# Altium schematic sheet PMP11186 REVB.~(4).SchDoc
size 431 x 279 mm; Date: Not shown in title block; ApprovedBy: Not shown in title block; CheckedBy: Not shown in title block; Author: Not shown in title block; CompanyName: Not shown in title block; Engineer: Not shown in title block; Organization: Not shown in title block; Address1: Not shown in title block; Address2: Not shown in title block; Address3: Not shown in title block; Address4: Not shown in title block; DocumentNumber: 1; Revision: Use project parameter SCH_Rev; SheetNumber: 1; SheetTotal: 1; PageSetup: Record=PageOptions¦CenterHorizontal=True¦CenterVertical=True¦PrintScale=1.00¦XCorrection=1.00¦YCorrection=1.00¦PrintKind=0¦BorderSize=5000000¦LeftOffset=0¦BottomOffset=0¦Orientation=2¦PaperLength=1000¦PaperWidth=1000¦Scale=100¦PaperSource=15¦PrintQuality=600¦MediaType=1¦DitherType=10¦PaperKind=Letter¦PrintScaleMode=1
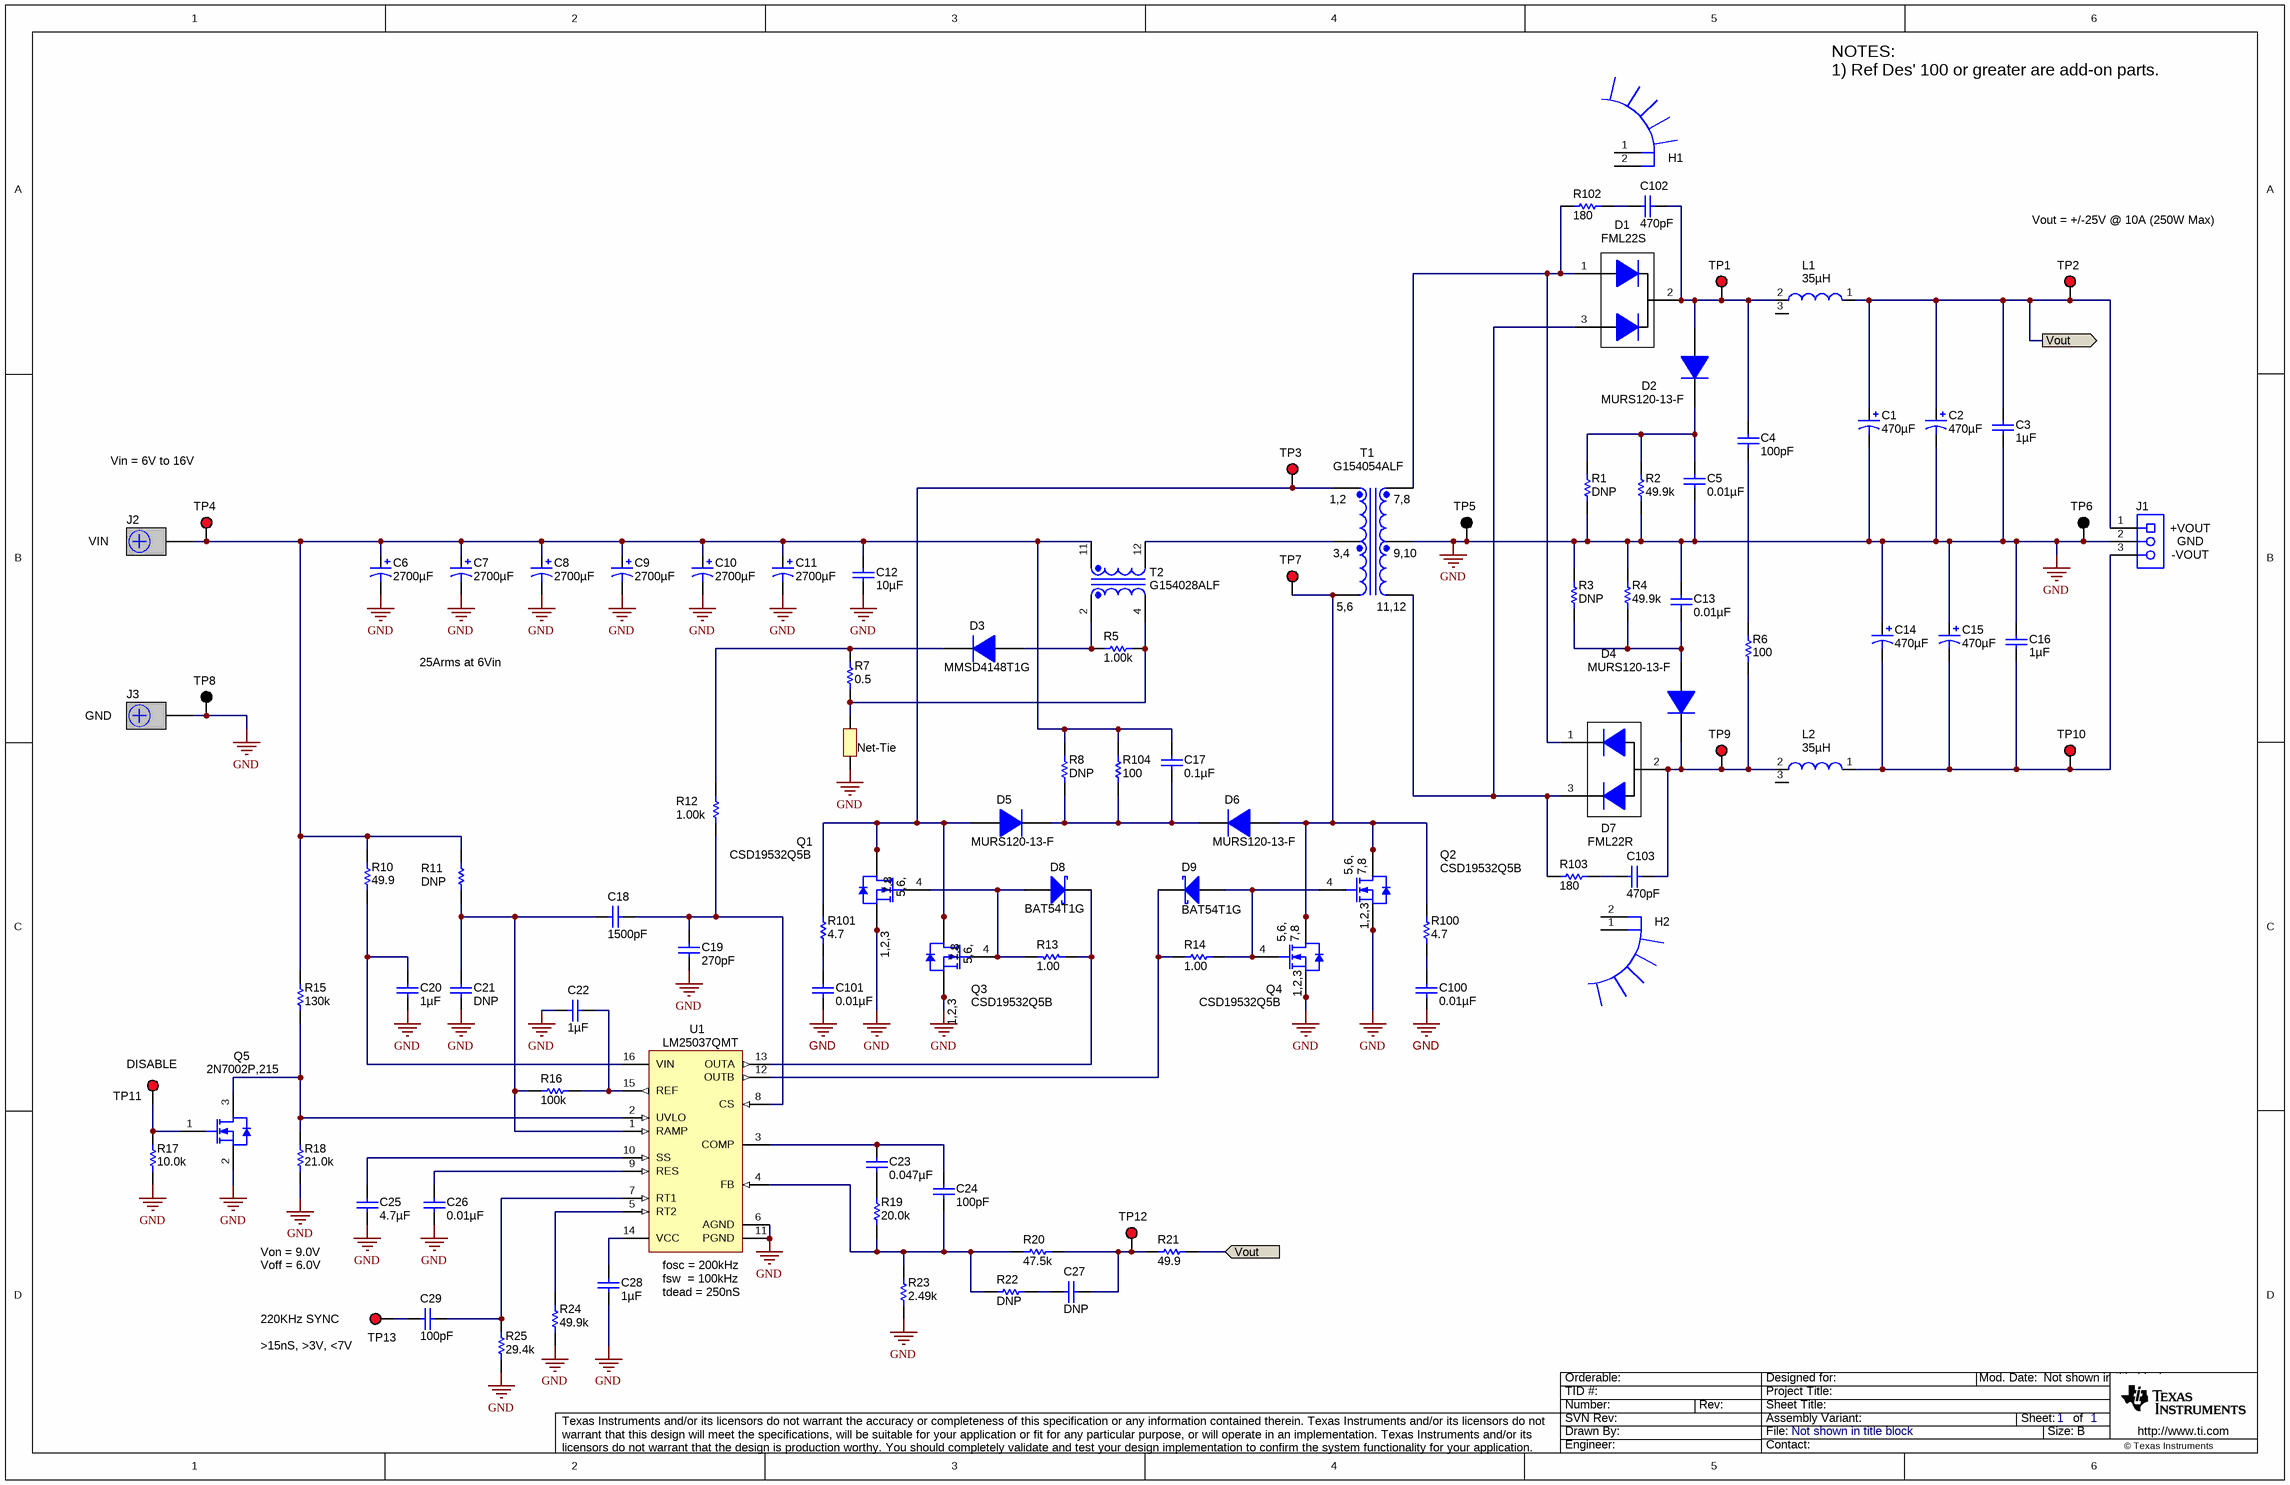
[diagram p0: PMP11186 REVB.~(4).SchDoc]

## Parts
C1  ValueDisplayed: 470µF  [CAPPR5-10X20]  (hidden comment: 35ZL470MEFC10X20)
C2  ValueDisplayed: 470µF  [CAPPR5-10X20]  (hidden comment: 35ZL470MEFC10X20)
C3  ValueDisplayed: 1µF  [0805_HV]  (hidden comment: GRM21BR71H105KA12L)
C4  ValueDisplayed: 100pF  [0805_HV]  (hidden comment: GRM21A5C2E101JW01D)
C5  ValueDisplayed: 0.01µF  [0805_HV]  (hidden comment: C2012X7R2A103M)
C6  ValueDisplayed: 2700µF  [ZLH_1250x2500]  (hidden comment: 25ZLH2700M12.5X35)
C7  ValueDisplayed: 2700µF  [ZLH_1250x2500]  (hidden comment: 25ZLH2700M12.5X35)
C8  ValueDisplayed: 2700µF  [ZLH_1250x2500]  (hidden comment: 25ZLH2700M12.5X35)
C9  ValueDisplayed: 2700µF  [ZLH_1250x2500]  (hidden comment: 25ZLH2700M12.5X35)
C10  ValueDisplayed: 2700µF  [ZLH_1250x2500]  (hidden comment: 25ZLH2700M12.5X35)
C11  ValueDisplayed: 2700µF  [ZLH_1250x2500]  (hidden comment: 25ZLH2700M12.5X35)
C12  ValueDisplayed: 10µF  [1210]  (hidden comment: C3225X7R1E106M)
C13  ValueDisplayed: 0.01µF  [0805_HV]  (hidden comment: C2012X7R2A103M)
C14  ValueDisplayed: 470µF  [CAPPR5-10X20]  (hidden comment: 35ZL470MEFC10X20)
C15  ValueDisplayed: 470µF  [CAPPR5-10X20]  (hidden comment: 35ZL470MEFC10X20)
C16  ValueDisplayed: 1µF  [0805_HV]  (hidden comment: GRM21BR71H105KA12L)
C17  ValueDisplayed: 0.1µF  [0805_145]  (hidden comment: C2012X7T2E104K125AA)
C18  ValueDisplayed: 1500pF  [0603]  (hidden comment: C1608C0G1H152J)
C19  ValueDisplayed: 270pF  [0603]  (hidden comment: C1608C0G1H271J)
C20  ValueDisplayed: 1µF  [0805_HV]  (hidden comment: C2012X7R1E105K)
C21  ValueDisplayed: DNP  [0603]
C22  ValueDisplayed: 1µF  [0603]  (hidden comment: C1608X7R1C105K)
C23  ValueDisplayed: 0.047µF  [0603]  (hidden comment: C1608X7R1H473K)
C24  ValueDisplayed: 100pF  [0603]  (hidden comment: C1608C0G1H101J)
C25  ValueDisplayed: 4.7µF  [0805_HV]  (hidden comment: C2012X7R1A475M)
C26  ValueDisplayed: 0.01µF  [0603]  (hidden comment: C1608X7R1H103K)
C27  ValueDisplayed: DNP  [0603]
C28  ValueDisplayed: 1µF  [0603]  (hidden comment: C1608X7R1C105K)
C29  ValueDisplayed: 100pF  [0603]  (hidden comment: C1608C0G1H101J)
C100  ValueDisplayed: 0.01µF  [0805_HV]  (hidden comment: C2012X7R2A103K)
C101  ValueDisplayed: 0.01µF  [0805_HV]  (hidden comment: C2012X7R2A103K)
C102  ValueDisplayed: 470pF  [0603]  (hidden comment: C1608C0G2E471J)
C103  ValueDisplayed: 470pF  [0603]  (hidden comment: C1608C0G2E471J)
D1  FML22S  [ITO-220AB]
D2  MURS120-13-F  [SMB]
D3  MMSD4148T1G  [SOD-123]
D4  MURS120-13-F  [SMB]
D5  MURS120-13-F  [SMB]
D6  MURS120-13-F  [SMB]
D7  FML22R  [ITO-220AB]
D8  BAT54T1G  [SOD-123]
D9  BAT54T1G  [SOD-123]
H1  513201B02500G  [HSINK_513201B02500]  (value not drawn)
H2  513201B02500G  [HSINK_513201B02500]  (value not drawn)
J1  OSTTA034163  [On-Shore_OSTTA034163]  (value not drawn)
J2  CB35-36-CY  [CB35-36-CY]  (value not drawn)
J3  CB35-36-CY  [CB35-36-CY]  (value not drawn)
L1  ValueDisplayed: 35µH  [B82559_1420]  (hidden comment: B82559A0353A020)
L2  ValueDisplayed: 35µH  [B82559_1420]  (hidden comment: B82559A0353A020)
NT1  Net-Tie  [Net-Tie_10mil]  (net tie, no BOM)
Q1  CSD19532Q5B  [TRANS_NexFET_Q5B]
Q2  CSD19532Q5B  [TRANS_NexFET_Q5B]
Q3  CSD19532Q5B  [TRANS_NexFET_Q5B]
Q4  CSD19532Q5B  [TRANS_NexFET_Q5B]
Q5  2N7002P,215  [SOT-23]
R1  ValueDisplayed: DNP  [1206]
R2  ValueDisplayed: 49.9k  [1206]  (hidden comment: CRCW120649K9FKEA)
R3  ValueDisplayed: DNP  [1206]
R4  ValueDisplayed: 49.9k  [1206]  (hidden comment: CRCW120649K9FKEA)
R5  ValueDisplayed: 1.00k  [0805_HV]  (hidden comment: CRCW08051K00FKEA)
R6  value 100  [1206]  (hidden comment: CRCW1206100RFKEA)
R7  ValueDisplayed: 0.5  [1206]  (hidden comment: CSR1206FKR500)
R8  ValueDisplayed: DNP  [2512]
R10  ValueDisplayed: 49.9  [0805_HV]  (hidden comment: CRCW080549R9FKEA)
R11  ValueDisplayed: DNP  [0603]
R12  ValueDisplayed: 1.00k  [0603]  (hidden comment: CRCW06031K00FKEA)
R13  value 1.00  [0603]  (hidden comment: CRCW06031R00FKEA)
R14  value 1.00  [0603]  (hidden comment: CRCW06031R00FKEA)
R15  ValueDisplayed: 130k  [0603]  (hidden comment: CRCW0603130KFKEA)
R16  ValueDisplayed: 100k  [0603]  (hidden comment: CRCW0603100KFKEA)
R17  value 10.0k  [0603]  (hidden comment: CRCW060310K0FKEA)
R18  ValueDisplayed: 21.0k  [0603]  (hidden comment: CRCW060321K0FKEA)
R19  ValueDisplayed: 20.0k  [0603]  (hidden comment: CRCW060320K0FKEA)
R20  ValueDisplayed: 47.5k  [0603]  (hidden comment: CRCW060347K5FKEA)
R21  ValueDisplayed: 49.9  [0603]  (hidden comment: CRCW060349R9FKEA)
R22  ValueDisplayed: DNP  [0603]
R23  value 2.49k  [0603]  (hidden comment: CRCW06032K49FKEA)
R24  ValueDisplayed: 49.9k  [0603]  (hidden comment: CRCW060349K9FKEA)
R25  ValueDisplayed: 29.4k  [0603]  (hidden comment: CRCW060329K4FKEA)
R100  ValueDisplayed: 4.7  [2512]  (hidden comment: CRCW25124R70JNEG)
R101  ValueDisplayed: 4.7  [2512]  (hidden comment: CRCW25124R70JNEG)
R102  ValueDisplayed: 180  [2512]  (hidden comment: CRCW2512180RFKEG)
R103  ValueDisplayed: 180  [2512]  (hidden comment: CRCW2512180RFKEG)
R104  ValueDisplayed: 100  [RESAR6600W80L4800T950H900]  (hidden comment: TMC010100R0FE02NI)
T1  G154054ALF  [GCI_G154027ALF]
T2  G154028ALF  [GCI_G154028ALF]
TP1  5000  [Keystone5000]  (value not drawn)
TP2  5000  [Keystone5000]  (value not drawn)
TP3  5000  [Keystone5000]  (value not drawn)
TP4  5000  [Keystone5000]  (value not drawn)
TP5  5001  [Keystone5001]  (value not drawn)
TP6  5001  [Keystone5001]  (value not drawn)
TP7  5000  [Keystone5000]  (value not drawn)
TP8  5001  [Keystone5001]  (value not drawn)
TP9  5000  [Keystone5000]  (value not drawn)
TP10  5000  [Keystone5000]  (value not drawn)
TP11  5000  [Keystone5000]  (value not drawn)
TP12  5000  [Keystone5000]  (value not drawn)
TP13  5000  [Keystone5000]  (value not drawn)
U1  LM25037QMT  [MTC16_N]

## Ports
Vout

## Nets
GND: C1.2(-) C2.2(-) C3.2 C5.2 C6.2(-) C7.2(-) C8.2(-) C9.2(-) C10.2(-) C11.2(-) C12.2 C13.1 C14.1(+) C15.1(+) C16.1 C19.1 C20.2 C21.1 C22.1 C25.2 C26.2 C28.2 C100.2 C101.2 J1.2 J3.1 NT1.2 Q1.1(S) Q1.2(S) Q1.3(S) Q2.1(S) Q2.2(S) Q2.3(S) Q3.1(S) Q3.2(S) Q3.3(S) Q4.1(S) Q4.2(S) Q4.3(S) Q5.2(S) R1.1 R2.1 R3.2 R4.2 R17.1 R18.1 R23.1 R24.1 R25.1 T1.2 TP5.1 TP6.1 TP8.1 U1.6(AGND) U1.11(PGND)
Vout: C1.1(+) C2.1(+) C3.1 J1.1 L1.1 R21.1 TP2.1 ; port Vout
NetC4_1: C4.1 C102.2 D1.2(K) D2.2(A) L1.2 TP1.1
NetC4_2: C4.2 R6.2
NetC5_1: C5.1 D2.1(K) R1.2 R2.2
NetC6_1: C6.1(+) C7.1(+) C8.1(+) C9.1(+) C10.1(+) C11.1(+) C12.1 C17.1 J2.1 R8.2 R10.2 R11.1 R15.2 R104.2 T2.11 TP4.1
NetC13_2: C13.2 D4.2(A) R3.1 R4.1
NetC14_2: C14.2(-) C15.2(-) C16.2 J1.3 L2.1 TP10.1
NetC17_2: C17.2 D5.1(K) D6.1(K) R8.1 R104.1
NetC18_1: C18.1 C21.2 R11.2 R16.2 U1.1(RAMP)
NetC18_2: C18.2 C19.2 R12.1 U1.8(CS)
NetC20_1: C20.1 R10.1 U1.16(VIN)
NetC22_2: C22.2 R16.1 U1.15(REF)
NetC23_1: C23.1 R19.2
NetC23_2: C23.2 C24.1 U1.3(COMP)
NetC24_2: C24.2 R19.1 R20.1 R22.1 R23.2 U1.4(FB)
NetC25_1: C25.1 U1.10(SS)
NetC26_1: C26.1 U1.9(RES)
NetC27_1: C27.1 R22.2
NetC27_2: C27.2 R20.2 R21.2 TP12.1
NetC28_1: C28.1 U1.14(VCC)
NetC29_1: C29.1 TP13.1
NetC29_2: C29.2 R25.2 U1.7(RT1)
NetC100_1: C100.1 R100.1
NetC101_1: C101.1 R101.1
NetC102_1: C102.1 R102.2
NetC103_1: C103.1 R103.2
NetC103_2: C103.2 D4.1(K) D7.2(A) L2.2 R6.1 TP9.1
NetD1_1: D1.1(A) D7.1(K) R102.1 T1.4
NetD1_3: D1.3(A) D7.3(K) R103.1 T1.6
NetD3_1: D3.1(K) R7.2 R12.2
NetD3_2: D3.2(A) R5.1 T2.2
NetD5_2: D5.2(A) Q1.5(D) Q1.6(D) Q1.7(D) Q1.8(D) Q3.5(D) Q3.6(D) Q3.7(D) Q3.8(D) R101.2 T1.1 TP3.1
NetD6_2: D6.2(A) Q2.5(D) Q2.6(D) Q2.7(D) Q2.8(D) Q4.5(D) Q4.6(D) Q4.7(D) Q4.8(D) R100.2 T1.3 TP7.1
NetD8_1: D8.1(K) R13.1 U1.13(OUTA)
NetD8_2: D8.2(A) Q1.4(G) Q3.4(G) R13.2
NetD9_1: D9.1(K) R14.1 U1.12(OUTB)
NetD9_2: D9.2(A) Q2.4(G) Q4.4(G) R14.2
NetNT1_1: NT1.1 R5.2 R7.1 T2.4
NetQ5_1: Q5.1(G) R17.2 TP11.1
NetQ5_3: Q5.3(D) R15.1 R18.2 U1.2(UVLO)
NetR24_2: R24.2 U1.5(RT2)
NetT1_5: T1.5 T2.12

Not connected (* = marked no-connect by the designer): H1 1 2; H2 1 2; L1 3; L2 3

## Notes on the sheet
- NOTES:
  1) Ref Des' 100 or greater are add-on parts.
- Vout = +/-25V @ 10A (250W Max)
- Vin = 6V to 16V
- VIN
- (near T1) 1,2
- (near T1) 3,4
- (near T1) 7,8
- (near T1) 9,10
- (near J1) +VOUT
- (near J1) -VOUT
- (near J1) GND
- (near T1) 5,6
- (near T1) 11,12
- 25Arms at 6Vin
- GND
- (near TP11) DISABLE
- Von = 9.0V
- Voff = 6.0V
- fsw  = 100kHz
- tdead = 250nS
- (near U1) fosc = 200kHz
- 220KHz SYNC
- (near TP13) >15nS, >3V, <7V

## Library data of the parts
C1 C2 C14 C15 = 35ZL470MEFC10X20: CAP, AL, 470 µF, 35 V, 0.023 Ohms, 1.82A, TH; Manufacturer: Rubycon; Polarized: Y; CompType: Capacitor; Value: 470uF; U/M: EA; Cap_F: 0.00047; Tolerance_%: 20; Value1: Unknown; VDC_V: 35; Value2: 35V; TaMin_C: -40; TaMax_C: 105; Cap_Case: 10x20
C3 C16 = GRM21BR71H105KA12L: CAP, CERM, 1uF, 50V, +/-10%, X7R, 0805; Manufacturer: MuRata; Polarized: N; CompType: Capacitor; U/M: EA; Cap_F: 0.000001; Tolerance_%: 10; VDC_V: 50; TaMin_C: -55; TaMax_C: 125; Cap_Case: 0805
C4 = GRM21A5C2E101JW01D: CAP, CERM, 100 pF, 250 V, +/- 5%, C0G/NP0, 0805; Manufacturer: MuRata; Polarized: N; CompType: Capacitor; Value: 100pF; U/M: EA; Cap_F: 0.0000000001; Tolerance_%: 5; Value1: Unknown; VDC_V: 250; Value2: 250V; TaMin_C: -55; TaMax_C: 125; Cap_Case: 0805
C5 C13 = C2012X7R2A103M: CAP, CERM, 0.01 µF, 100 V, +/- 20%, X7R, 0805; Manufacturer: TDK; Polarized: N; CompType: Capacitor; Value: 0.01uF; U/M: EA; Cap_F: 0.00000001; Tolerance_%: 20; ESR_ohm: 0.0571; Value1: 0.0571 ohm; VDC_V: 100; Value2: 100V; TaMin_C: -55; TaMax_C: 125; Cap_Case: 0805
C6-C11 = 63ZLH470M12.5X25: CAP, AL, 2700 µF, 25 V, 0.016 ohm, 4.12A, TH; Manufacturer: Rubycon; Polarized: Y; CompType: Capacitor; Value: 2700uF; U/M: EA; Cap_F: 0.00047; Tolerance_%: 20; Value2: 25V; ESR_ohm: 0.043; IRMS_A: 1.99; TaMin_C: -40; TaMax_C: 105
C12 = C3225X7R1E106M: CAP, CERM, 10 µF, 25 V, +/- 20%, X7R, 1210; Manufacturer: TDK; Polarized: N; CompType: Capacitor; Value: 10uF; U/M: EA; Cap_F: 0.00001; Tolerance_%: 20; ESR_ohm: 0.0027; Value1: 0.0027 ohm; VDC_V: 25; Value2: 25V; IRMS_A: 3; TaMin_C: -55; TaMax_C: 125
C17 = C2012X7T2E104K125AA: CAP, CERM, 0.1 µF, 250 V, +/- 10%, X7T, 0805; Manufacturer: TDK; Polarized: N; CompType: Capacitor; Value: 0.1uF; U/M: EA; Cap_F: 0.0000001; Tolerance_%: 10; Value1: Unknown; VDC_V: 250; Value2: 250V; TaMin_C: -55; TaMax_C: 125; Cap_Case: 0805; AEC Category: Q200
C18 = C1608C0G1H152J: CAP, CERM, 1500 pF, 50 V, +/- 5%, C0G/NP0, 0603; Manufacturer: TDK; Polarized: N; CompType: Capacitor; Value: 1500pF; U/M: EA; Cap_F: 0.0000000015; Tolerance_%: 5; ESR_ohm: 0.039; Value1: 0.039 ohm; VDC_V: 50; Value2: 50V; TaMin_C: -55; TaMax_C: 125
C19 = C1608C0G1H271J: CAP, CERM, 270 pF, 50 V, +/- 5%, C0G/NP0, 0603; Manufacturer: TDK; Polarized: N; CompType: Capacitor; Value: 270pF; U/M: EA; Cap_F: 0.00000000027; Tolerance_%: 5; ESR_ohm: 0.0949; Value1: 0.0949 ohm; VDC_V: 50; Value2: 50V; TaMin_C: -55; TaMax_C: 125; AEC Category: Q200
C20 = C2012X7R1E105K: CAP, CERM, 1 µF, 25 V, +/- 10%, X7R, 0805; Manufacturer: TDK; Polarized: N; CompType: Capacitor; Value: 1uF; U/M: EA; Cap_F: 0.000001; Tolerance_%: 10; ESR_ohm: 0.0075; Value1: 0.0075 ohm; VDC_V: 25; Value2: 25V; TaMin_C: -55; TaMax_C: 125; Cap_Case: 0805
C21 C27 = C1608C0G1H271J: CAP, DNP, 0603; Polarized: N; CompType: Capacitor; U/M: EA; Cap_F: 0.00000000027; Tolerance_%: 5; ESR_ohm: 0.0949; VDC_V: 50; Value2: 50V; TempCo: C0G/NP0; TaMin_C: -55; TaMax_C: 125
C22 C28 = C1608X7R1C105K: CAP, CERM, 1 µF, 16 V, +/- 10%, X7R, 0603; Manufacturer: TDK; Polarized: N; CompType: Capacitor; Value: 1uF; U/M: EA; Cap_F: 0.000001; Tolerance_%: 10; ESR_ohm: 0.0057; Value1: 0.0057 ohm; VDC_V: 16; Value2: 16V; TaMin_C: -55; TaMax_C: 125
C23 = C1608X7R1H473K: CAP, CERM, 0.047 µF, 50 V, +/- 10%, X7R, 0603; Manufacturer: TDK; Polarized: N; CompType: Capacitor; Value: 0.047uF; U/M: EA; Cap_F: 0.000000047; Tolerance_%: 10; ESR_ohm: 0.0234; Value1: 0.0234 ohm; VDC_V: 50; Value2: 50V; TaMin_C: -55; TaMax_C: 125
C24 = C1608C0G1H101J: CAP, CERM, 100 pF, 50 V, +/- 5%, C0G/NP0, 0603; Manufacturer: TDK; Polarized: N; CompType: Capacitor; Value: 100pF; U/M: EA; Cap_F: 0.0000000001; Tolerance_%: 5; ESR_ohm: 0.1679; Value1: 0.1679 ohm; VDC_V: 50; Value2: 50V; TaMin_C: -55; TaMax_C: 125; AEC Category: Q200
C25 = C2012X7R1A475M: CAP, CERM, 4.7 µF, 10 V, +/- 20%, X7R, 0805; Manufacturer: TDK; Polarized: N; CompType: Capacitor; Value: 4.7uF; U/M: EA; Cap_F: 0.0000047; Tolerance_%: 20; Value1: Unknown; VDC_V: 10; Value2: 10V; TaMin_C: -55; TaMax_C: 125; Cap_Case: 0805; AEC Category: Q200
C26 = C1608X7R1H103K: CAP, CERM, 0.01 µF, 50 V, +/- 10%, X7R, 0603; Manufacturer: TDK; Polarized: N; CompType: Capacitor; Value: 0.01uF; U/M: EA; Cap_F: 0.00000001; Tolerance_%: 10; ESR_ohm: 0.0539; Value1: 0.0539 ohm; VDC_V: 50; Value2: 50V; TaMin_C: -55; TaMax_C: 125
C29 = C1608C0G1H101J: CAP, CERM, 100 pF, 50 V, +/- 5%, C0G/NP0, 0603; Manufacturer: TDK; Polarized: N; CompType: Capacitor; Value: 100pF; U/M: EA; Cap_F: 0.0000000001; Tolerance_%: 5; ESR_ohm: 0.1679; Value1: 0.1679 ohm; VDC_V: 50; Value2: 50V; TaMin_C: -55; TaMax_C: 125
C100 C101 = C2012X7R2A103K: CAP, CERM, 0.01 µF, 100 V, +/- 10%, X7R, 0805; Manufacturer: TDK; Polarized: N; CompType: Capacitor; Value: 0.01uF; U/M: EA; Cap_F: 0.00000001; Tolerance_%: 10; ESR_ohm: 0.0571; Value1: 0.0571 ohm; VDC_V: 100; Value2: 100V; TaMin_C: -55; TaMax_C: 125; Cap_Case: 0805; AEC Category: Q200
C102 C103 = C1608C0G2E471J: CAP, CERM, 470 pF, 250 V, +/- 5%, C0G/NP0, 0603; Manufacturer: TDK; Polarized: N; CompType: Capacitor; Value: 470pF; U/M: EA; Cap_F: 0.00000000047; Tolerance_%: 5; ESR_ohm: 0.0714; Value1: 0.0714 ohm; VDC_V: 250; Value2: 250V; TaMin_C: -55; TaMax_C: 125; AEC Category: Q200
D1 = FML22S: Diode, Ultrafast, 200 V, 10 A, TH; Manufacturer: Thinki Semiconductor; U/M: EA; Vf_V: 0.98; Value: 200V; Value1: 10A; Value2: 0.98V; Io_A: 10; Vr_V: 200; TJmax_C: 150; RJC_CperW: 4
D2 D4-D6 = MURS120-13-F: Diode, Superfast Rectifier, 200 V, 1 A, SMB; Manufacturer: Diodes Inc.; U/M: EA; Vf_V: 0.875; Value: 200V; Value1: 1A; Value2: 0.875V; Io_A: 1; Vr_V: 200; TJmax_C: 175
D3 = MMSD4148T1G: Diode, Switching, 100 V, 0.2 A, SOD-123; Manufacturer: ON Semiconductor; U/M: EA; Vf_V: 1; Value: 100V; Value1: 0.2A; Value2: 1V; Io_A: 0.2; Vr_V: 100; TJmax_C: 150
D7 = FML22R: Diode, Ultrafast, 200 V, 10 A, TH; Manufacturer: Thinki Semiconductor; SymbolCreator: Altium; U/M: EA; Vf_V: 0.98; Value: 200V; Value1: 10A; Value2: 0.98V; Io_A: 10; Vr_V: 200; TJmax_C: 150; RJC_CperW: 4
D8 D9 = BAT54T1G: Diode, Schottky, 30V, 0.2A, SOD-123; Manufacturer: ON Semi; Value: 0.8V; U/M: EA; Vf_V: 0.8; Io_A: 0.2; Vr_V: 30; TJmax_C: 125; RJC_CperW: 174
H1 H2 = 513201B02500G: HEATSINK TO-218/TO-247 W/PINS 2"; Manufacturer: Aavid; SymbolCreator: a0799628
J1 = OSTTA034163: Terminal Block, 3x1, 5.08 mm, 15A, TH; Manufacturer: On-Shore Technology; SymbolCreator: a0412235; U/M: EA
J2 J3 = CB35-36-CY: Terminal 50A Lug; Manufacturer: Panduit; SymbolCreator: crossc; CompType: Screw Terminal; U/M: EA
L1 L2 = B82559A0353A020: Inductor, Wirewound, Ferrite, 35 µH, 9.3 A, 0.007 ohm, SMD; Manufacturer: TDK; SymbolCreator: a0411947; Ind_H: 35.0E-6; Value: 35uH; Imax_A: 9.3; Isat: 9.3A @ 15% inductance drop; DCR_ohm: 0.007; Value2: 9.3A
NT1 = Net-Tie: Single point connection between nets.; SymbolCreator: codlsc
Q1-Q4 = CSD19532Q5B: MOSFET, N-CH, 100 V, 17 A, SON 5x6mm; Manufacturer: Texas Instruments; Alternate Manufacturer: None; U/M: EA; ChType: N; Value: 100V; VdsMax_V: 100; Value1: ? ohm; Value2: 48 nC; QgTyp_nC: 48; Vgs_V: 20; IdsMax_A: 17; AEC Category: Q101
Q5 = 2N7002P,215: MOSFET, N-CH, 60 V, 0.36 A, SOT-23; Manufacturer: NXP Semiconductor; Alternate Manufacturer: None; U/M: EA; ChType: N; Value: 60V; VdsMax_V: 60; Value1: 2 ohm; Rdson45_ohm: 2; Value2: 0.6 nC; QgTyp_nC: 0.6; Vgs_V: 20; IdsMax_A: 0.36
R1 R3 = CRCW120649K9FKEA: RES, DNP, 1206; CompType: Resistor; Res_ohm: 49900; Tolerance_%: 1; Value1: 1%; Power_W: 0.25; Value2: 0.25W; TempCo: 100 ppm/C; EIA_Code: E96; U/M: EA
R2 R4 = CRCW120649K9FKEA: RES, 49.9 k, 1%, 0.25 W, 1206; Manufacturer: Vishay-Dale; CompType: Resistor; Value: 49.9k; Res_ohm: 49900; Value_Code: 49k9; Tolerance_%: 1; Power_W: 0.25; Value2: 0.25W; VDC_V: 200; TempCo: 100 ppm/C; EIA_Code: E96; U/M: EA
R5 = CRCW08051K00FKEA: RES, 1.00 k, 1%, 0.125 W, 0805; Manufacturer: Vishay-Dale; CompType: Resistor; Value: 1.00k; Res_ohm: 1000; Value_Code: 1k00; Tolerance_%: 1; Power_W: 0.125; Value2: 0.125W; VDC_V: 150; TempCo: 100 ppm/C; EIA_Code: E96; U/M: EA
R6 = CRCW1206100RFKEA: RES, 100 ohm, 1%, 0.25W, 1206; Manufacturer: Vishay-Dale; CompType: Resistor; Value_Code: 100R; Tolerance_%: 1; Power_W: 0.25; VDC_V: 200; TempCo: 100 ppm/C; EIA_Code: E96; U/M: EA
R7 = CSR1206FKR500: RES, 0.5, 1%, 0.5 W, 1206; Manufacturer: Stackpole Electronics Inc; CompType: Resistor; Value: 0.5; Value_Code: R500; Tolerance_%: 1; Value2: 0.5W; TempCo: 100 ppm/C; U/M: EA; AEC Category: Q200
R8 = CRCW251210K0JNEG: RES, DNP, 2512; CompType: Resistor; Res_ohm: 10000; Tolerance_%: 5; Value1: 5%; Power_W: 1; Value2: 1W; TempCo: 200 ppm/C; EIA_Code: E24; U/M: EA
R10 = CRCW080549R9FKEA: RES, 49.9, 1%, 0.125 W, 0805; Manufacturer: Vishay-Dale; CompType: Resistor; Value: 49.9; Value_Code: 49R9; Tolerance_%: 1; Power_W: 0.125; Value2: 0.125W; VDC_V: 150; TempCo: 100 ppm/C; EIA_Code: E96; U/M: EA; AEC Category: Q200
R11 R22 = CRCW060332K4FKEA: RES, DNP, 0603; CompType: Resistor; Res_ohm: 32400; Tolerance_%: 1; Value1: 1%; Power_W: 0.1; Value2: 0.1W; TempCo: 100 ppm/C; EIA_Code: E96; U/M: EA
R12 = CRCW06031K00FKEA: RES, 1.00 k, 1%, 0.1 W, 0603; Manufacturer: Vishay-Dale; CompType: Resistor; Value: 1.00k; Res_ohm: 1000; Value_Code: 1k00; Tolerance_%: 1; Power_W: 0.1; Value2: 0.1W; VDC_V: 75; TempCo: 100 ppm/C; EIA_Code: E96; U/M: EA
R13 R14 = CRCW06031R00FKEA: RES, 1.00 ohm, 1%, 0.1W, 0603; Manufacturer: Vishay-Dale; CompType: Resistor; Res_ohm: 1; Value_Code: 1R00; Power_W: 0.1; VDC_V: 75; TempCo: 100 ppm/C; EIA_Code: E96; U/M: EA
R15 = CRCW0603130KFKEA: RES, 130 k, 1%, 0.1 W, 0603; Manufacturer: Vishay-Dale; CompType: Resistor; Value: 130k; Res_ohm: 130000; Tolerance_%: 1; Power_W: 0.1; Value2: 0.1W; VDC_V: 75; TempCo: 100 ppm/C; EIA_Code: E96; U/M: EA
R16 = CRCW0603100KFKEA: RES, 100 k, 1%, 0.1 W, 0603; Manufacturer: Vishay-Dale; CompType: Resistor; Value: 100k; Res_ohm: 100000; Tolerance_%: 1; Power_W: 0.1; Value2: 0.1W; VDC_V: 75; TempCo: 100 ppm/C; EIA_Code: E96; U/M: EA; AEC Category: Q200
R17 = CRCW060310K0FKEA: RES, 10.0k ohm, 1%, 0.1W, 0603; Manufacturer: Vishay-Dale; CompType: Resistor; Res_ohm: 10000; Value_Code: 10k0; Tolerance_%: 1; Power_W: 0.1; VDC_V: 75; TempCo: 100 ppm/C; EIA_Code: E96; U/M: EA
R18 = CRCW060321K0FKEA: RES, 21.0 k, 1%, 0.1 W, 0603; Manufacturer: Vishay-Dale; CompType: Resistor; Value: 21.0k; Res_ohm: 21000; Value_Code: 21k0; Tolerance_%: 1; Power_W: 0.1; Value2: 0.1W; VDC_V: 75; TempCo: 100 ppm/C; EIA_Code: E96; U/M: EA
R19 = CRCW060320K0FKEA: RES, 20.0 k, 1%, 0.1 W, 0603; Manufacturer: Vishay-Dale; CompType: Resistor; Value: 20.0k; Res_ohm: 20000; Value_Code: 20k0; Tolerance_%: 1; Power_W: 0.1; Value2: 0.1W; VDC_V: 75; TempCo: 100 ppm/C; EIA_Code: E96; U/M: EA; AEC Category: Q200
R20 = CRCW060347K5FKEA: RES, 47.5 k, 1%, 0.1 W, 0603; Manufacturer: Vishay-Dale; CompType: Resistor; Value: 47.5k; Res_ohm: 47500; Value_Code: 47k5; Tolerance_%: 1; Power_W: 0.1; Value2: 0.1W; VDC_V: 75; TempCo: 100 ppm/C; EIA_Code: E96; U/M: EA
R21 = CRCW060349R9FKEA: RES, 49.9, 1%, 0.1 W, 0603; Manufacturer: Vishay-Dale; CompType: Resistor; Value: 49.9; Value_Code: 49R9; Tolerance_%: 1; Power_W: 0.1; Value2: 0.1W; VDC_V: 75; TempCo: 100 ppm/C; EIA_Code: E96; U/M: EA
R23 = CRCW06032K49FKEA: RES, 2.49k ohm, 1%, 0.1W, 0603; Manufacturer: Vishay-Dale; CompType: Resistor; Res_ohm: 2490; Value_Code: 2k49; Tolerance_%: 1; Power_W: 0.1; VDC_V: 75; TempCo: 100 ppm/C; EIA_Code: E96; U/M: EA
R24 = CRCW060349K9FKEA: RES, 49.9 k, 1%, 0.1 W, 0603; Manufacturer: Vishay-Dale; CompType: Resistor; Value: 49.9k; Res_ohm: 49900; Value_Code: 49k9; Tolerance_%: 1; Power_W: 0.1; Value2: 0.1W; VDC_V: 75; TempCo: 100 ppm/C; EIA_Code: E96; U/M: EA
R25 = CRCW060329K4FKEA: RES, 29.4 k, 1%, 0.1 W, 0603; Manufacturer: Vishay-Dale; CompType: Resistor; Value: 29.4k; Res_ohm: 29400; Value_Code: 29k4; Tolerance_%: 1; Power_W: 0.1; Value2: 0.1W; VDC_V: 75; TempCo: 100 ppm/C; EIA_Code: E96; U/M: EA
R100 R101 = CRCW25124R70JNEG: RES, 4.7, 5%, 1 W, 2512; Manufacturer: Vishay-Dale; CompType: Resistor; Value: 4.7; Value_Code: 4R70; Tolerance_%: 5; Power_W: 1; Value2: 1W; VDC_V: 500; TempCo: 200 ppm/C; EIA_Code: E24; U/M: EA; AEC Category: Q200
R102 R103 = CRCW2512180RFKEG: RES, 180, 1%, 1 W, 2512; Manufacturer: Vishay-Dale; CompType: Resistor; Value: 180; Value_Code: 180R; Tolerance_%: 1; Value2: 1W; VDC_V: 500; TempCo: 100 ppm/C; U/M: EA; AEC Category: Q200
R104 = SQP10AJB-7R5: RES, 100, 1%, 12.5 W, RES 35x20x10mm; Manufacturer: Vishay; CompType: Resistor; Value: 100; Tolerance_%: 5; Power_W: 12.5; Value2: 12.5W; U/M: EA; AEC Category: Q200
T1 = G154027ALF: Transformer, 4.7 uH, TH; Manufacturer: GCI Technologies; SymbolCreator: Altium; DCR_Ohm: 0.00038; Value: 50 uH; LeakageL: 0.6 uH; U/M: EA
T2 = G154028ALF: Transformer, 22.4 mH, SMT; Manufacturer: GCI Technologies; SymbolCreator: Altium; DCR_Ohm: 0.00042; Value: 22.4 mH; U/M: EA
TP1-TP4 TP7 TP9-TP13 = 5000: Test Point, Miniature, Red, TH; Manufacturer: Keystone; CompType: Test Point Loop; U/M: EA
TP5 TP6 TP8 = 5001: Test Point, Miniature, Black, TH; Manufacturer: Keystone; CompType: Test Point Loop; U/M: EA
U1 = LM25037QMT: Dual-Mode PWM Controller With Alternating Outputs, Automotive Grade, 16-pin TSSOP; Manufacturer: Texas Instruments; PackageTopMarking: NSUZXYTT*M25037*MT; PowerWise: Y; CompType: Switcher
